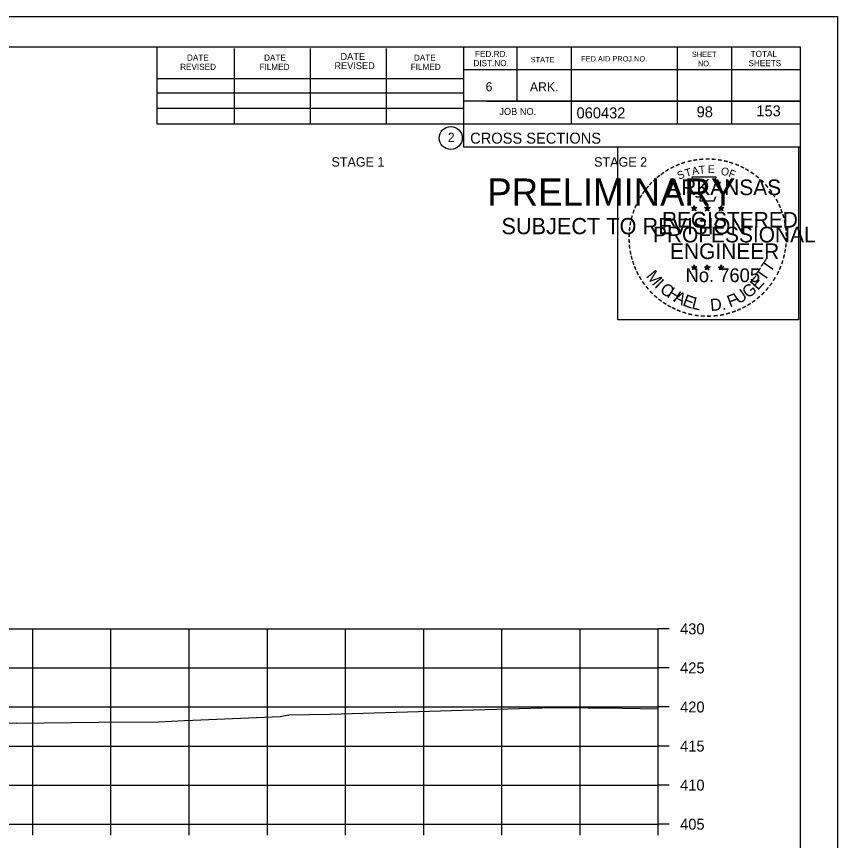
# Model space of a CAD drawing. Extents: x 1538688 to 1540766, y 656250 to 671912.
# Drawn here: x 1538916.1 to 1539021.1, y 661352.6 to 661458 of the extents above; entities that cross this region are included whole.
import ezdxf

# ---------------------------------------------------------------- set-up
doc = ezdxf.new("R2010")
doc.units = 0
for name, color, linetype in [('18', 7, 'Continuous'), ('22', 7, 'Continuous'), ('26', 7, 'Continuous'), ('7', 7, 'Continuous'), ('8', 7, 'Continuous'), ('9', 7, 'Continuous'), ('Borings', 7, 'Continuous'), ('Default', 7, 'Continuous'), ('Horizontal Alignment', 7, 'Continuous'), ('RipRap', 7, 'Continuous')]:
    doc.layers.add(name, color=color, linetype=linetype)

msp = doc.modelspace()

# ---------------------------------------------------------------- linework, layer by layer
at = {"layer": '18'}
msp.add_lwpolyline([(1538907.72, 661367.81), (1538916.1, 661367.56), (1538916.14, 661367.56), (1538926.62, 661367.73), (1538934.25, 661367.74), (1538937.57, 661367.92), (1538938.65, 661367.95), (1538949.83, 661368.42), (1538950.91, 661368.66), (1538956.2, 661368.72), (1538974.56, 661369.28), (1538984.84, 661369.57), (1538993.62, 661369.48), (1538998.18, 661369.43)], dxfattribs=at)
at = {"layer": '22'}
for p, q in [((1538718.18, 661379.65), (1538998.18, 661379.65)), ((1538918.18, 661354.65), (1538918.18, 661379.65)), ((1538928.18, 661354.65), (1538928.18, 661379.65)), ((1538938.18, 661354.65), (1538938.18, 661379.65)), ((1538948.18, 661354.65), (1538948.18, 661379.65)), ((1538958.18, 661354.65), (1538958.18, 661379.65)), ((1538968.18, 661354.65), (1538968.18, 661379.65)), ((1538978.18, 661354.65), (1538978.18, 661379.65)), ((1538988.18, 661354.65), (1538988.18, 661379.65)), ((1538998.18, 661354.65), (1538998.18, 661379.65)), ((1538718.18, 661374.65), (1538998.18, 661374.65)), ((1538718.18, 661369.65), (1538998.18, 661369.65)), ((1538718.18, 661364.65), (1538998.18, 661364.65)), ((1538718.18, 661359.65), (1538998.18, 661359.65)), ((1538718.18, 661354.65), (1538998.18, 661354.65))]:
    msp.add_line(p, q, dxfattribs=at)
at = {"layer": '26'}
msp.add_line((1538687.78, 661458.01), (1539021.11, 661458.01), dxfattribs=at)
for points in [[(1538687.77, 661458.01), (1539021.11, 661458.01), (1539021.11, 661244.67), (1538687.77, 661244.67)], [(1538993.03, 661441.35), (1539016.13, 661441.35), (1539016.13, 661419.2), (1538993.03, 661419.2)]]:
    msp.add_lwpolyline(points, close=True, dxfattribs=at)
at = {"layer": '8'}
for p, q in [((1539002.79, 661433.81), (1539002.75, 661433.56)), ((1539002.79, 661433.45), (1539002.79, 661433.81)), ((1539002.79, 661433.81), (1539002.84, 661433.56)), ((1539004.46, 661433.81), (1539004.42, 661433.56)), ((1539004.46, 661433.45), (1539004.46, 661433.81)), ((1539004.46, 661433.81), (1539004.51, 661433.56)), ((1539006.22, 661433.8), (1539006.18, 661433.55)), ((1539006.22, 661433.44), (1539006.22, 661433.8)), ((1539006.22, 661433.8), (1539006.27, 661433.55)), ((1539002.44, 661433.56), (1539002.79, 661433.45)), ((1539002.44, 661433.56), (1539002.69, 661433.52)), ((1539002.44, 661433.56), (1539002.68, 661433.44)), ((1539002.57, 661433.15), (1539002.79, 661433.45)), ((1539002.57, 661433.15), (1539002.7, 661433.4)), ((1539002.57, 661433.15), (1539002.79, 661433.37)), ((1539003.13, 661433.56), (1539002.79, 661433.45)), ((1539003, 661433.15), (1539002.79, 661433.45)), ((1539003, 661433.15), (1539002.79, 661433.37)), ((1539003.13, 661433.56), (1539002.85, 661433.51)), ((1539003, 661433.15), (1539002.86, 661433.44)), ((1539003.13, 661433.56), (1539002.93, 661433.46)), ((1539004.11, 661433.56), (1539004.46, 661433.45)), ((1539004.11, 661433.56), (1539004.36, 661433.52)), ((1539004.11, 661433.56), (1539004.35, 661433.44)), ((1539004.24, 661433.15), (1539004.46, 661433.45)), ((1539004.24, 661433.15), (1539004.37, 661433.4)), ((1539004.24, 661433.15), (1539004.46, 661433.37)), ((1539004.8, 661433.56), (1539004.46, 661433.45)), ((1539004.67, 661433.15), (1539004.46, 661433.45)), ((1539004.67, 661433.15), (1539004.46, 661433.37)), ((1539004.8, 661433.56), (1539004.52, 661433.51)), ((1539004.67, 661433.15), (1539004.53, 661433.44)), ((1539004.8, 661433.56), (1539004.6, 661433.46)), ((1539005.87, 661433.55), (1539006.22, 661433.44)), ((1539005.87, 661433.55), (1539006.13, 661433.5)), ((1539005.87, 661433.55), (1539006.11, 661433.43)), ((1539006.01, 661433.14), (1539006.22, 661433.44)), ((1539006.01, 661433.14), (1539006.13, 661433.38)), ((1539006.01, 661433.14), (1539006.22, 661433.36)), ((1539006.57, 661433.55), (1539006.22, 661433.44)), ((1539006.43, 661433.14), (1539006.22, 661433.44)), ((1539006.43, 661433.14), (1539006.22, 661433.35)), ((1539006.57, 661433.55), (1539006.28, 661433.5)), ((1539006.43, 661433.14), (1539006.3, 661433.43)), ((1539006.57, 661433.55), (1539006.36, 661433.45)), ((1539002.43, 661425.99), (1539002.78, 661425.88)), ((1539002.43, 661425.99), (1539002.69, 661425.94)), ((1539002.43, 661425.99), (1539002.67, 661425.87)), ((1539002.57, 661425.58), (1539002.78, 661425.88)), ((1539002.57, 661425.58), (1539002.69, 661425.82)), ((1539002.57, 661425.58), (1539002.78, 661425.8)), ((1539002.78, 661426.24), (1539002.74, 661425.99)), ((1539002.78, 661425.88), (1539002.78, 661426.24)), ((1539002.78, 661426.24), (1539002.83, 661425.99)), ((1539003.13, 661425.99), (1539002.78, 661425.88)), ((1539003, 661425.58), (1539002.78, 661425.88)), ((1539003, 661425.58), (1539002.78, 661425.79)), ((1539003.13, 661425.99), (1539002.84, 661425.94)), ((1539003, 661425.58), (1539002.86, 661425.87)), ((1539003.13, 661425.99), (1539002.93, 661425.89)), ((1539004.1, 661425.99), (1539004.45, 661425.88)), ((1539004.1, 661425.99), (1539004.36, 661425.94)), ((1539004.1, 661425.99), (1539004.34, 661425.87)), ((1539004.24, 661425.58), (1539004.45, 661425.88)), ((1539004.24, 661425.58), (1539004.36, 661425.82)), ((1539004.24, 661425.58), (1539004.45, 661425.8)), ((1539004.45, 661426.24), (1539004.41, 661425.99)), ((1539004.45, 661425.88), (1539004.45, 661426.24)), ((1539004.45, 661426.24), (1539004.5, 661425.99)), ((1539004.8, 661425.99), (1539004.45, 661425.88)), ((1539004.67, 661425.58), (1539004.45, 661425.88)), ((1539004.67, 661425.58), (1539004.45, 661425.79)), ((1539004.8, 661425.99), (1539004.51, 661425.94)), ((1539004.67, 661425.58), (1539004.53, 661425.87)), ((1539004.8, 661425.99), (1539004.6, 661425.89)), ((1539005.87, 661425.98), (1539006.22, 661425.87)), ((1539005.87, 661425.98), (1539006.12, 661425.93)), ((1539005.87, 661425.98), (1539006.11, 661425.86)), ((1539006, 661425.57), (1539006.22, 661425.87)), ((1539006, 661425.57), (1539006.13, 661425.81)), ((1539006, 661425.57), (1539006.22, 661425.79)), ((1539006.22, 661426.23), (1539006.18, 661425.98)), ((1539006.22, 661425.87), (1539006.22, 661426.23)), ((1539006.22, 661426.23), (1539006.27, 661425.98)), ((1539006.57, 661425.98), (1539006.22, 661425.87)), ((1539006.43, 661425.57), (1539006.22, 661425.87)), ((1539006.43, 661425.57), (1539006.22, 661425.78)), ((1539006.57, 661425.98), (1539006.28, 661425.93)), ((1539006.43, 661425.57), (1539006.3, 661425.86)), ((1539006.57, 661425.98), (1539006.36, 661425.88))]:
    msp.add_line(p, q, dxfattribs=at)
for points in [[(1539002.48, 661437.44), (1539002.75, 661436.61)], [(1539005.99, 661436.52), (1539006.13, 661436.8), (1539005.45, 661436.78), (1539005.6, 661437.44), (1539002.48, 661437.44)], [(1539002.97, 661435.02), (1539002.97, 661434.93), (1539003.53, 661434.91), (1539003.48, 661434.44), (1539005.35, 661434.44), (1539005.55, 661434.97)], [(1539002.79, 661433.81), (1539003, 661433.15), (1539002.44, 661433.56), (1539003.13, 661433.56), (1539002.57, 661433.15), (1539002.79, 661433.81)], [(1539004.46, 661433.81), (1539004.67, 661433.15), (1539004.11, 661433.56), (1539004.8, 661433.56), (1539004.24, 661433.15), (1539004.46, 661433.81)], [(1539006.22, 661433.8), (1539006.43, 661433.14), (1539005.87, 661433.55), (1539006.57, 661433.55), (1539006.01, 661433.14), (1539006.22, 661433.8)], [(1539002.78, 661426.24), (1539003, 661425.58), (1539002.43, 661425.99), (1539003.13, 661425.99), (1539002.57, 661425.58), (1539002.78, 661426.24)], [(1539004.45, 661426.24), (1539004.67, 661425.58), (1539004.1, 661425.99), (1539004.8, 661425.99), (1539004.24, 661425.58), (1539004.45, 661426.24)], [(1539006.22, 661426.23), (1539006.43, 661425.57), (1539005.87, 661425.98), (1539006.57, 661425.98), (1539006, 661425.57), (1539006.22, 661426.23)]]:
    msp.add_lwpolyline(points, dxfattribs=at)
for centre, radius in [((1539002.79, 661433.45), 0.172), ((1539002.79, 661433.45), 0.145), ((1539002.79, 661433.45), 0.116), ((1539002.79, 661433.45), 0.0991), ((1539002.79, 661433.45), 0.0747), ((1539002.79, 661433.45), 0.0495), ((1539002.79, 661433.45), 0.0296), ((1539004.46, 661433.45), 0.172), ((1539004.46, 661433.45), 0.145), ((1539004.46, 661433.45), 0.116), ((1539004.46, 661433.45), 0.0991), ((1539004.46, 661433.45), 0.0747), ((1539004.46, 661433.45), 0.0495), ((1539004.46, 661433.45), 0.0296), ((1539006.22, 661433.44), 0.172), ((1539006.22, 661433.44), 0.145), ((1539006.22, 661433.44), 0.116), ((1539006.22, 661433.44), 0.0991), ((1539006.22, 661433.44), 0.0747), ((1539006.22, 661433.44), 0.0495), ((1539006.22, 661433.44), 0.0296), ((1539002.78, 661425.88), 0.172), ((1539002.78, 661425.88), 0.145), ((1539002.78, 661425.88), 0.116), ((1539002.78, 661425.88), 0.0991), ((1539002.78, 661425.88), 0.0747), ((1539002.78, 661425.88), 0.0495), ((1539002.78, 661425.88), 0.0296), ((1539004.45, 661425.88), 0.172), ((1539004.45, 661425.88), 0.145), ((1539004.45, 661425.88), 0.116), ((1539004.45, 661425.88), 0.0991), ((1539004.45, 661425.88), 0.0747), ((1539004.45, 661425.88), 0.0495), ((1539004.45, 661425.88), 0.0296), ((1539006.22, 661425.87), 0.172), ((1539006.22, 661425.87), 0.145), ((1539006.22, 661425.87), 0.116), ((1539006.22, 661425.87), 0.0991), ((1539006.22, 661425.87), 0.0747), ((1539006.22, 661425.87), 0.0495), ((1539006.22, 661425.87), 0.0296)]:
    msp.add_circle(centre, radius, dxfattribs=at)
at = {"layer": 'Borings'}
for p, q in [((1538998.18, 661354.65), (1538998.18, 661379.65)), ((1538999.58, 661379.65), (1538998.18, 661379.65)), ((1538999.58, 661374.65), (1538998.18, 661374.65)), ((1538999.58, 661369.65), (1538998.18, 661369.65)), ((1538999.58, 661364.65), (1538998.18, 661364.65)), ((1538999.58, 661359.65), (1538998.18, 661359.65)), ((1538718.18, 661354.65), (1538998.18, 661354.65)), ((1538918.18, 661353.25), (1538918.18, 661354.65)), ((1538928.18, 661353.25), (1538928.18, 661354.65)), ((1538938.18, 661353.25), (1538938.18, 661354.65)), ((1538948.18, 661353.25), (1538948.18, 661354.65)), ((1538958.18, 661353.25), (1538958.18, 661354.65)), ((1538968.18, 661353.25), (1538968.18, 661354.65)), ((1538978.18, 661353.25), (1538978.18, 661354.65)), ((1538988.18, 661353.25), (1538988.18, 661354.65)), ((1538998.18, 661353.25), (1538998.18, 661354.65)), ((1538999.58, 661354.65), (1538998.18, 661354.65))]:
    msp.add_line(p, q, dxfattribs=at)
at = {"layer": 'RipRap'}
for p, q in [((1538700.18, 661454.11), (1539016.36, 661454.11)), ((1538934.1, 661444.23), (1538934.1, 661454.11)), ((1538943.96, 661444.23), (1538943.96, 661453.91)), ((1538953.72, 661444.23), (1538953.72, 661453.91)), ((1538963.4, 661444.23), (1538963.4, 661453.91)), ((1538973.26, 661454.11), (1538973.26, 661441.31)), ((1538980.1, 661454.11), (1538980.1, 661447.17)), ((1538987.04, 661454.11), (1538987.04, 661444.23)), ((1539000.62, 661454.11), (1539000.62, 661444.23)), ((1539007.56, 661454.11), (1539007.56, 661444.23)), ((1539016.36, 661248.65), (1539016.36, 661454.11)), ((1539016.36, 661451.17), (1538973.26, 661451.17)), ((1539016.36, 661451.19), (1539016.36, 661451.19)), ((1538934.1, 661450.09), (1538973.26, 661450.09)), ((1538934.1, 661448.23), (1538973.26, 661448.23)), ((1539016.36, 661447.17), (1538973.26, 661447.17)), ((1538976.22, 661447.17), (1539016.36, 661447.17)), ((1538934.1, 661444.23), (1538934.1, 661446.29)), ((1538934.1, 661446.29), (1538973.26, 661446.29)), ((1539016.36, 661444.23), (1538934.1, 661444.23)), ((1538973.26, 661441.31), (1539016.36, 661441.31))]:
    msp.add_line(p, q, dxfattribs=at)
msp.add_circle((1538971.64, 661442.45), 1.47, dxfattribs=at)

# ---------------------------------------------------------------- texts
at = {"layer": '7'}
for s, p in [('98', (1539003.09, 661445.11)), ('153', (1539010.73, 661445.23))]:
    msp.add_text(s, height=1.4, dxfattribs=at).set_placement(p)
at = {"layer": '8'}
for s, height, rotation, p in [('-', 1.6, 24.3072, (1539000.59, 661438.3)), ('-', 1.6, 19.1761, (1539001.23, 661438.57)), ('-', 1.6, 13.6301, (1539001.98, 661438.81)), ('-', 1.6, 10.2193, (1539002.66, 661438.97)), ('-', 1.6, 5.8968, (1539003.38, 661439.08)), ('-', 1.6, 0.1862, (1539004.16, 661439.15)), ('E', 1, 0.8323, (1539004.53, 661437.97)), ('-', 1.6, 357.743, (1539004.88, 661439.14)), ('-', 1.6, 352.1617, (1539005.62, 661439.08)), ('-', 1.6, 347.2049, (1539006.34, 661438.97)), ('-', 1.6, 342.3362, (1539006.98, 661438.81)), ('-', 1.6, 337.8551, (1539007.71, 661438.59)), ('-', 1.6, 36.2317, (1538998.79, 661437.21)), ('-', 1.6, 34.0636, (1538999.36, 661437.61)), ('-', 1.6, 28.7918, (1538999.96, 661437.98)), ('S', 1, 21.594, (1539000.83, 661437.12)), ('T', 1, 16.4036, (1539001.75, 661437.45)), ('A', 1, 11.2132, (1539002.57, 661437.7)), ('T', 1, 6.0228, (1539003.42, 661437.86)), ('O', 1, 350.4515, (1539006.13, 661437.76)), ('F', 1, 340.0707, (1539007.09, 661437.54)), ('-', 1.6, 334.1211, (1539008.34, 661438.32)), ('-', 1.6, 329.6409, (1539008.92, 661438.04)), ('-', 1.6, 325.8627, (1539009.57, 661437.67)), ('-', 1.6, 48.423, (1538997.43, 661435.94)), ('-', 1.6, 42.9622, (1538997.88, 661436.42)), ('-', 1.6, 38.9507, (1538998.31, 661436.84)), ('ARKANSAS', 2, 360, (1538999.33, 661435.15)), ('-', 1.6, 320.5297, (1539010.18, 661437.25)), ('-', 1.6, 315.5786, (1539010.77, 661436.76)), ('-', 1.6, 50.6142, (1538997.03, 661435.46)), ('-', 1.6, 309.8797, (1539011.34, 661436.21)), ('-', 1.6, 306.6522, (1539011.87, 661435.61)), ('-', 1.6, 58.0706, (1538996.29, 661434.36)), ('-', 1.6, 54.2325, (1538996.61, 661434.89)), ('-', 1.4, 303.6753, (1539012.35, 661435.04)), ('-', 1.6, 67.7743, (1538995.72, 661433.14)), ('-', 1.6, 62.8713, (1538995.97, 661433.75)), ('-', 1.6, 299.6684, (1539012.67, 661434.43)), ('-', 1.6, 294.6628, (1539013, 661433.82)), ('-', 1.6, 72.3945, (1538995.5, 661432.51)), ('REGISTERED', 2, 360, (1538998.65, 661431)), ('DWB', 0.01, 360, (1539002.77, 661433.44)), ('DWB', 0.01, 360, (1539004.44, 661433.44)), ('DWB', 0.01, 360, (1539006.21, 661433.43)), ('-', 1.6, 290.5728, (1539013.25, 661433.24)), ('-', 1.6, 285.1233, (1539013.49, 661432.66)), ('-', 1.6, 81.2013, (1538995.17, 661431.08)), ('-', 1.6, 75.461, (1538995.3, 661431.79)), ('-', 1.6, 280.5493, (1539013.69, 661431.92)), ('-', 1.6, 85.1863, (1538995.09, 661430.39)), ('PROFESSIONAL', 2, 360, (1538997.51, 661429.1)), ('-', 1.6, 276.5962, (1539013.85, 661431.15)), ('-', 1.6, 94.1959, (1538995.1, 661428.96)), ('-', 1.6, 89.0622, (1538995.07, 661429.69)), ('-', 1.6, 274.3301, (1539013.91, 661430.43)), ('-', 1.6, 269.9407, (1539013.94, 661429.8)), ('-', 1.6, 98.9479, (1538995.17, 661428.3)), ('ENGINEER', 2, 360, (1538999.69, 661426.97)), ('-', 1.6, 263.5172, (1539013.93, 661429.13)), ('-', 1.6, 101.7149, (1538995.31, 661427.56)), ('-', 1.6, 105.4578, (1538995.47, 661426.97)), ('-', 1.6, 255.7626, (1539013.74, 661427.8)), ('-', 1.6, 260.9953, (1539013.85, 661428.48)), ('-', 1.6, 109.0874, (1538995.69, 661426.34)), ('T', 1.54, 55.055, (1539012.5, 661425.14)), ('-', 1.6, 252.8681, (1539013.56, 661427.08)), ('-', 1.6, 114.0643, (1538995.94, 661425.74)), ('-', 1.6, 115.7289, (1538996.24, 661425.12)), ('M', 1.54, 308.9175, (1538996.55, 661424.77)), ('No. 7605', 1.757, 360, (1539001.67, 661424.02)), ('DWB', 0.01, 360, (1539002.77, 661425.87)), ('DWB', 0.01, 360, (1539004.44, 661425.87)), ('DWB', 0.01, 360, (1539006.2, 661425.86)), ('T', 1.54, 55.055, (1539011.77, 661424.02)), ('-', 1.6, 244.6197, (1539013.08, 661425.78)), ('-', 1.6, 247.8887, (1539013.34, 661426.41)), ('-', 1.6, 120.4471, (1538996.6, 661424.54)), ('I', 1.54, 316.4636, (1538997.6, 661423.45)), ('E', 1.54, 48.7313, (1539010.93, 661422.89)), ('-', 1.6, 239.0712, (1539012.68, 661425.03)), ('-', 1.6, 125.8934, (1538997, 661423.98)), ('-', 1.6, 130.7181, (1538997.47, 661423.42)), ('C', 1.54, 324.0197, (1538998.27, 661422.82)), ('H', 1.54, 327.5342, (1538999.18, 661422.17)), ('U', 1.54, 34.4052, (1539008.47, 661421.14)), ('G', 1.54, 38.2173, (1539009.67, 661421.87)), ('-', 1.6, 231.2538, (1539011.85, 661423.81)), ('-', 1.6, 233.8452, (1539012.28, 661424.38)), ('-', 1.6, 134.2238, (1538997.98, 661422.88)), ('-', 1.6, 138.9338, (1538998.51, 661422.41)), ('A', 1.54, 332.5513, (1539000.03, 661421.63)), ('E', 1.54, 339.2068, (1539001.19, 661421.07)), ('F', 1.54, 20.8202, (1539007.34, 661420.75)), ('-', 1.6, 221.0851, (1539010.85, 661422.74)), ('-', 1.6, 225.7653, (1539011.37, 661423.25)), ('-', 1.6, 144.6463, (1538999.06, 661422.01)), ('-', 1.6, 148.0898, (1538999.63, 661421.64)), ('-', 1.6, 151.5704, (1539000.2, 661421.31)), ('L', 1.54, 346.2929, (1539002.38, 661420.65)), ('D.', 1.54, 5.2602, (1539004.89, 661420.31)), ('-', 1.6, 212.2491, (1539009.77, 661421.88)), ('-', 1.6, 215.7363, (1539010.3, 661422.26)), ('-', 1.6, 154.6002, (1539000.73, 661421.07)), ('-', 1.6, 158.5612, (1539001.35, 661420.81)), ('-', 1.6, 162.7983, (1539002.04, 661420.6)), ('-', 1.6, 167.5555, (1539002.75, 661420.43)), ('-', 1.6, 195.4743, (1539007.29, 661420.7)), ('-', 1.6, 200.7184, (1539007.97, 661420.94)), ('-', 1.6, 204.2516, (1539008.59, 661421.21)), ('-', 1.6, 207.3568, (1539009.21, 661421.53)), ('-', 1.6, 173.1155, (1539003.52, 661420.32)), ('-', 1.6, 176.5183, (1539004.27, 661420.27)), ('-', 1.6, 181.5918, (1539005.02, 661420.29)), ('-', 1.6, 185.8167, (1539005.83, 661420.37)), ('-', 1.6, 191.2858, (1539006.56, 661420.5))]:
    msp.add_text(s, height=height, rotation=rotation, dxfattribs=at).set_placement(p)
at = {"layer": '9'}
for s, height, p in [('PRELIMINARY', 3.5, (1538976.31, 661433.78)), ('DWB', 0.01, (1538977.06, 661435.63)), ('SUBJECT TO REVISION', 2.0751, (1538978.12, 661430.15))]:
    msp.add_text(s, height=height, rotation=360, dxfattribs=at).set_placement(p)
at = {"layer": 'Default'}
for s, p in [('STAGE 1', (1538956.38, 661438.8)), ('STAGE 2', (1538989.98, 661438.8))]:
    msp.add_text(s, height=1.2, dxfattribs=at).set_placement(p)
at = {"layer": 'Horizontal Alignment'}
for s, p in [('430', (1539000.98, 661378.95)), ('425', (1539000.98, 661373.95)), ('420', (1539000.98, 661368.95)), ('415', (1539000.98, 661363.95)), ('410', (1539000.98, 661358.95)), ('405', (1539000.98, 661353.95))]:
    msp.add_text(s, height=1.4, dxfattribs=at).set_placement(p)
at = {"layer": 'RipRap'}
for s, height, p in [('DATE', 0.782, (1538937.9, 661452.35)), ('DATE', 0.782, (1538947.76, 661452.35)), ('DATE', 0.879, (1538957.54, 661452.45)), ('DATE', 0.782, (1538966.92, 661452.35)), ('FED.RD.', 0.782, (1538974.74, 661452.83)), ('STATE', 0.684, (1538981.86, 661452.15)), ('FED.AID PROJ.NO.', 0.684, (1538988.32, 661452.25)), ('SHEET', 0.684, (1539002.48, 661452.83)), ('TOTAL', 0.782, (1539010, 661452.83)), ('REVISED', 0.782, (1538937.02, 661451.17)), ('FILMED', 0.782, (1538947.18, 661451.17)), ('REVISED', 0.879, (1538956.76, 661451.27)), ('FILMED', 0.782, (1538966.52, 661451.17)), ('DIST.NO.', 0.782, (1538974.54, 661451.65)), ('NO.', 0.684, (1539003.26, 661451.65)), ('SHEETS', 0.782, (1539009.72, 661451.65)), ('6', 1.17, (1538976.1, 661448.43)), ('ARK.', 1.172, (1538981.76, 661448.43)), ('060432', 1.4, (1538987.73, 661444.97)), ('JOB NO.', 0.879, (1538977.86, 661445.41)), ('2', 1.17, (1538971.26, 661441.96)), ('CROSS SECTIONS', 1.4, (1538974.12, 661441.74))]:
    msp.add_text(s, height=height, rotation=360, dxfattribs=at).set_placement(p)

doc.saveas('drawing.dxf')
